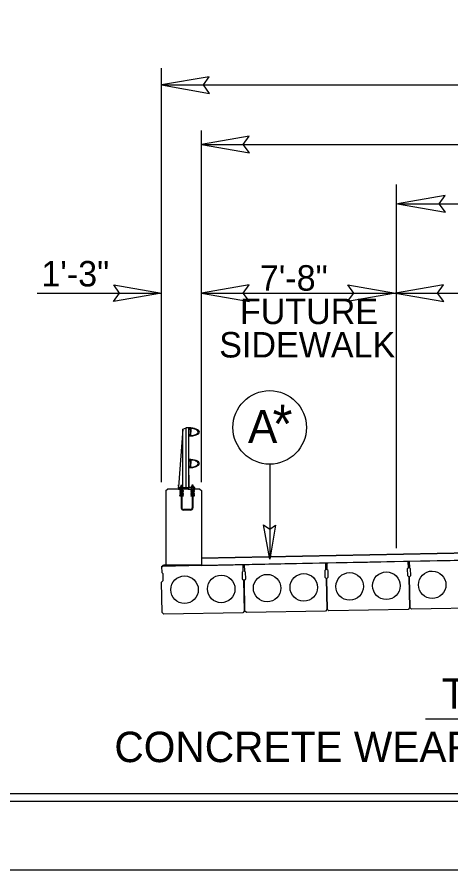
# Model space of a CAD drawing. Extents: x 573732 to 574187, y -53389 to -53257.
# Drawn here: x 573830.28 to 573847.31, y -53388.95 to -53355.48 of the extents above; entities that cross this region are included whole.
import ezdxf

# ---------------------------------------------------------------- set-up
doc = ezdxf.new("R2010")
doc.units = 0
for name, color, linetype in [('Old_Level_60', 7, 'Continuous'), ('Prop Dimension', 7, 'Continuous'), ('Prop Retaining Wall', 7, 'Continuous'), ('Prop Shade Light', 7, 'Continuous'), ('Sheet Cutting Line CELL', 7, 'Continuous'), ('Sheet Plot Border Inside CELL', 7, 'Continuous'), ('Sheet Plot Border Outside CELL', 7, 'Continuous'), ('Sheet Typical CELL', 7, 'Continuous'), ('Typical Bridge Rail Two Bar CELL', 7, 'Continuous'), ('Typical ID Circle CELL', 7, 'Continuous'), ('Typical Pavement Slope CELL', 7, 'Continuous'), ('Typical Pavement Slope Information CELL', 7, 'Continuous'), ('Typical Terminator CELL', 7, 'Continuous'), ('Typical Text ID Circle CELL', 7, 'Continuous'), ('Typical Text Label CELL', 7, 'Continuous')]:
    doc.layers.add(name, color=color, linetype=linetype)

# ---------------------------------------------------------------- blocks, each defined once
blk = doc.blocks.new('BRIDGE RAIL 2 BAR LEFT')
at = {"layer": 'Typical Bridge Rail Two Bar CELL'}
for p, q in [((-2.94, 21.39), (-2.37, 21.57)), ((-1.99, 21.57), (-2.37, 21.57)), ((-2.37, 12.16), (-2.37, 21.57)), ((-1.99, 12.16), (-1.99, 21.57)), ((-1.68, 21.42), (-1.68, 20.91)), ((-2.94, 21.39), (-3.6, 12.34)), ((-2.94, 12.16), (-2.94, 21.39)), ((-1.68, 20.39), (-1.68, 20.91)), ((-2.94, 17.07), (-2.96, 17.07)), ((-1.68, 16.48), (-1.68, 15.97)), ((-1.68, 15.46), (-1.68, 15.97)), ((-3.6, 12.16), (-3.6, 12.34)), ((-3.58, 12.45), (-3.58, 12.62)), ((-3.02, 12.54), (-3.23, 12.54)), ((-3.23, 12.54), (-3.23, 12.36)), ((-3.23, 11.74), (-3.23, 12.16)), ((-3.02, 12.36), (-3.02, 12.54)), ((-3.02, 11.74), (-3.02, 12.16)), ((-1.5, 11.79), (-1.5, 12.2)), ((-1.27, 12.59), (-1.49, 12.59)), ((-1.49, 12.59), (-1.49, 12.41)), ((-1.27, 12.41), (-1.27, 12.59)), ((-1.26, 11.79), (-1.26, 12.2)), ((-5.59, 11.72), (-5.35, 11.97)), ((-5.59, 11.72), (-5.59, 0)), ((-0.24, 11.97), (-5.35, 11.97)), ((-2.88, 11.79), (-3.38, 11.79)), ((-2.88, 11.73), (-3.38, 11.73)), ((-3.17, 11.57), (-3.38, 11.57)), ((-3.17, 11.51), (-3.38, 11.51)), ((-3.17, 11.34), (-3.38, 11.34)), ((-3.17, 11.29), (-3.38, 11.29)), ((-3.17, 11.12), (-3.38, 11.12)), ((-3.17, 11.07), (-3.38, 11.07)), ((-3.17, 10.9), (-3.38, 10.9)), ((-3.17, 10.84), (-3.38, 10.84)), ((-3.17, 11.68), (-3.27, 11.68)), ((-3.17, 11.62), (-3.27, 11.62)), ((-3.17, 11.45), (-3.27, 11.45)), ((-3.17, 11.4), (-3.27, 11.4)), ((-3.17, 11.23), (-3.27, 11.23)), ((-3.17, 11.18), (-3.27, 11.18)), ((-3.17, 11.01), (-3.27, 11.01)), ((-3.17, 10.95), (-3.27, 10.95)), ((-3.09, 11.68), (-3.17, 11.68)), ((-3.17, 11.68), (-3.17, 9.02)), ((-2.99, 11.68), (-3.09, 11.68)), ((-3.09, 11.68), (-3.09, 9.02)), ((-2.99, 11.62), (-3.09, 11.62)), ((-2.88, 11.57), (-3.09, 11.57)), ((-2.88, 11.51), (-3.09, 11.51)), ((-2.99, 11.45), (-3.09, 11.45)), ((-2.99, 11.4), (-3.09, 11.4)), ((-2.88, 11.34), (-3.09, 11.34)), ((-2.88, 11.29), (-3.09, 11.29)), ((-2.99, 11.23), (-3.09, 11.23)), ((-2.99, 11.18), (-3.09, 11.18)), ((-2.88, 11.12), (-3.09, 11.12)), ((-2.88, 11.07), (-3.09, 11.07)), ((-2.99, 11.01), (-3.09, 11.01)), ((-2.99, 10.95), (-3.09, 10.95)), ((-2.88, 10.9), (-3.09, 10.9)), ((-2.88, 10.84), (-3.09, 10.84)), ((-1.14, 11.79), (-1.64, 11.79)), ((-1.14, 11.73), (-1.64, 11.73)), ((-1.43, 11.57), (-1.64, 11.57)), ((-1.43, 11.51), (-1.64, 11.51)), ((-1.43, 11.34), (-1.64, 11.34)), ((-1.43, 11.29), (-1.64, 11.29)), ((-1.43, 11.12), (-1.64, 11.12)), ((-1.43, 11.07), (-1.64, 11.07)), ((-1.43, 10.9), (-1.64, 10.9)), ((-1.43, 10.84), (-1.64, 10.84)), ((-1.43, 11.68), (-1.53, 11.68)), ((-1.43, 11.62), (-1.53, 11.62)), ((-1.43, 11.45), (-1.53, 11.45)), ((-1.43, 11.4), (-1.53, 11.4)), ((-1.43, 11.23), (-1.53, 11.23)), ((-1.43, 11.18), (-1.53, 11.18)), ((-1.43, 11.01), (-1.53, 11.01)), ((-1.43, 10.95), (-1.53, 10.95)), ((-1.34, 11.68), (-1.43, 11.68)), ((-1.43, 11.68), (-1.43, 9.02)), ((-1.25, 11.68), (-1.34, 11.68)), ((-1.34, 11.68), (-1.34, 9.02)), ((-1.25, 11.62), (-1.34, 11.62)), ((-1.14, 11.57), (-1.34, 11.57)), ((-1.14, 11.51), (-1.34, 11.51)), ((-1.25, 11.45), (-1.34, 11.45)), ((-1.25, 11.4), (-1.34, 11.4)), ((-1.14, 11.34), (-1.34, 11.34)), ((-1.14, 11.29), (-1.34, 11.29)), ((-1.25, 11.23), (-1.34, 11.23)), ((-1.25, 11.18), (-1.34, 11.18)), ((-1.14, 11.12), (-1.34, 11.12)), ((-1.14, 11.07), (-1.34, 11.07)), ((-1.25, 11.01), (-1.34, 11.01)), ((-1.25, 10.95), (-1.34, 10.95)), ((-1.14, 10.9), (-1.34, 10.9)), ((-1.14, 10.84), (-1.34, 10.84)), ((-0.24, 11.97), (0, 11.72)), ((0, 11.72), (0, 0)), ((-1.69, 8.76), (-2.82, 8.76)), ((-1.69, 8.67), (-2.82, 8.67)), ((-6.19, -0.27), (-5.95, 0)), ((-5.54, 0), (-5.95, 0)), ((0, 0), (-5.54, 0))]:
    blk.add_line(p, q, dxfattribs=at)
for points in [[(-1.99, 20.25), (-1.99, 20.5), (-1.89, 20.5), (-1.89, 20.46), (-1.9, 20.46), (-1.9, 20.36), (-1.74, 20.36), (-1.72, 20.51), (-1.72, 20.91), (-1.72, 21.3), (-1.74, 21.46), (-1.9, 21.46), (-1.9, 21.36), (-1.89, 21.36), (-1.89, 21.31), (-1.99, 21.31), (-1.99, 21.56)], [(-1.99, 15.32), (-1.99, 15.56), (-1.89, 15.56), (-1.89, 15.52), (-1.9, 15.52), (-1.9, 15.42), (-1.74, 15.42), (-1.72, 15.58), (-1.72, 15.97), (-1.72, 16.37), (-1.74, 16.52), (-1.9, 16.52), (-1.9, 16.42), (-1.89, 16.42), (-1.89, 16.38), (-1.99, 16.38), (-1.99, 16.62)], [(-1.03, 11.97), (-1.03, 12.2), (-1.9, 12.2), (-1.9, 14.14), (-1.99, 14.14), (-1.99, 12.16), (-3.55, 12.16), (-3.55, 12.3), (-3.6, 12.3), (-3.6, 11.97), (-2.85, 11.97), (-2.85, 12.1), (-2.09, 12.1), (-2.09, 11.97), (-1.03, 11.97)], [(-2.91, 12.15), (-2.91, 12.2), (-3.12, 12.2), (-3.34, 12.2), (-3.34, 12.15)], [(-2.97, 12.2), (-2.97, 12.33), (-2.99, 12.36), (-3.25, 12.36), (-3.28, 12.33), (-3.28, 12.2), (-2.97, 12.2), (-3.07, 12.2), (-3.07, 12.33), (-3.04, 12.36), (-3.07, 12.33), (-3.1, 12.36), (-3.15, 12.36), (-3.18, 12.33), (-3.18, 12.2), (-3.18, 12.33), (-3.2, 12.36)], [(-1.16, 12.2), (-1.16, 12.25), (-1.38, 12.25), (-1.59, 12.25), (-1.59, 12.2)], [(-1.22, 12.24), (-1.22, 12.38), (-1.25, 12.41), (-1.51, 12.41), (-1.54, 12.38), (-1.54, 12.24), (-1.22, 12.24), (-1.33, 12.24), (-1.33, 12.38), (-1.3, 12.41), (-1.33, 12.38), (-1.35, 12.41), (-1.41, 12.41), (-1.43, 12.38), (-1.43, 12.24), (-1.43, 12.38), (-1.46, 12.41)], [(-3.38, 11.79), (-3.38, 11.73), (-3.27, 11.68), (-3.27, 11.62), (-3.38, 11.57), (-3.38, 11.51), (-3.27, 11.45), (-3.27, 11.4), (-3.38, 11.34), (-3.38, 11.29), (-3.27, 11.23), (-3.27, 11.18), (-3.38, 11.12), (-3.38, 11.07), (-3.27, 11.01), (-3.27, 10.95), (-3.38, 10.9), (-3.38, 10.84)], [(-2.88, 11.79), (-2.88, 11.73), (-2.99, 11.68), (-2.99, 11.62), (-2.88, 11.57), (-2.88, 11.51), (-2.99, 11.45), (-2.99, 11.4), (-2.88, 11.34), (-2.88, 11.29), (-2.99, 11.23), (-2.99, 11.18), (-2.88, 11.12), (-2.88, 11.07), (-2.99, 11.01), (-2.99, 10.95), (-2.88, 10.9), (-2.88, 10.84)], [(-1.64, 11.79), (-1.64, 11.73), (-1.53, 11.68), (-1.53, 11.62), (-1.64, 11.57), (-1.64, 11.51), (-1.53, 11.45), (-1.53, 11.4), (-1.64, 11.34), (-1.64, 11.29), (-1.53, 11.23), (-1.53, 11.18), (-1.64, 11.12), (-1.64, 11.07), (-1.53, 11.01), (-1.53, 10.95), (-1.64, 10.9), (-1.64, 10.84)], [(-1.14, 11.79), (-1.14, 11.73), (-1.25, 11.68), (-1.25, 11.62), (-1.14, 11.57), (-1.14, 11.51), (-1.25, 11.45), (-1.25, 11.4), (-1.14, 11.34), (-1.14, 11.29), (-1.25, 11.23), (-1.25, 11.18), (-1.14, 11.12), (-1.14, 11.07), (-1.25, 11.01), (-1.25, 10.95), (-1.14, 10.9), (-1.14, 10.84)]]:
    blk.add_lwpolyline(points, dxfattribs=at)
for centre in [(-3.34, 10.98), (-1.18, 10.98)]:
    blk.add_circle(centre, 0.0417, dxfattribs=at)
for centre, radius, start, end in [((-1.64, 21.42), 0.0392, 90, 180), ((-1.64, 20.4), 0.0392, 180, 270), ((-1.64, 16.48), 0.0392, 90, 180), ((-1.64, 15.46), 0.0392, 180, 270), ((-2.82, 9.02), 0.35, 180, 270), ((-2.82, 9.02), 0.267, 180, 270), ((-1.7, 9.02), 0.267, 270, 0), ((-1.69, 9.02), 0.35, 270, 0)]:
    blk.add_arc(centre, radius, start, end, dxfattribs=at)
for centre, major_axis, ratio, start_param, end_param in [((-1.99, 20.91), (1.67, 0), 0.39036, 6.282787, 7.853967), ((-1.64, 20.91), (1.11, 0), 0.495501, 6.282718, 7.853881), ((-1.99, 20.91), (1.67, 0), 0.39036, 4.712404, 6.282787), ((-1.64, 20.91), (1.11, 0), 0.495501, 4.712489, 6.282718), ((-1.99, 15.97), (1.67, 0), 0.39036, 6.282787, 7.853967), ((-1.64, 15.97), (1.11, 0), 0.495501, 6.282718, 7.853881), ((-1.99, 15.97), (1.67, 0), 0.39036, 4.712404, 6.282787), ((-1.64, 15.97), (1.11, 0), 0.495501, 4.712489, 6.282718)]:
    blk.add_ellipse(centre, major_axis=major_axis, ratio=ratio, start_param=start_param, end_param=end_param, dxfattribs=at)

msp = doc.modelspace()

# ---------------------------------------------------------------- linework, layer by layer
at = {"layer": 'Old_Level_60'}
for points in [[(573845.686, -53376.834), (573847.274, -53376.802), (573848.86, -53376.77), (573848.866, -53377.041), (573848.833, -53377.074), (573848.838, -53377.334), (573848.906, -53377.4), (573848.93, -53378.593), (573848.864, -53378.662), (573845.759, -53378.722), (573845.69, -53378.657), (573845.666, -53377.465), (573845.733, -53377.396), (573845.727, -53377.135), (573845.692, -53377.104), (573845.686, -53376.834)], [(573835.966, -53377.025), (573837.554, -53376.994), (573839.139, -53376.962), (573839.145, -53377.233), (573839.113, -53377.266), (573839.117, -53377.525), (573839.186, -53377.592), (573839.209, -53378.785), (573839.144, -53378.854), (573836.039, -53378.914), (573835.969, -53378.849), (573835.945, -53377.657), (573836.013, -53377.588), (573836.007, -53377.327), (573835.972, -53377.296), (573835.966, -53377.025)], [(573839.206, -53376.962), (573840.794, -53376.931), (573842.379, -53376.899), (573842.385, -53377.169), (573842.353, -53377.203), (573842.357, -53377.462), (573842.426, -53377.528), (573842.449, -53378.722), (573842.384, -53378.79), (573839.279, -53378.851), (573839.209, -53378.785), (573839.185, -53377.594), (573839.253, -53377.524), (573839.247, -53377.264), (573839.212, -53377.233), (573839.206, -53376.962)], [(573842.446, -53376.897), (573844.034, -53376.866), (573845.62, -53376.833), (573845.626, -53377.104), (573845.593, -53377.138), (573845.598, -53377.397), (573845.666, -53377.463), (573845.69, -53378.657), (573845.624, -53378.725), (573842.519, -53378.786), (573842.45, -53378.72), (573842.426, -53377.528), (573842.493, -53377.459), (573842.487, -53377.199), (573842.452, -53377.168), (573842.446, -53376.897)]]:
    msp.add_lwpolyline(points, dxfattribs=at)
for centre in [(573836.852, -53377.953), (573838.292, -53377.924), (573840.092, -53377.89), (573841.532, -53377.861), (573843.333, -53377.824), (573844.773, -53377.796), (573846.573, -53377.761)]:
    msp.add_ellipse(centre, major_axis=(0.001, 0.54), ratio=0.999904, dxfattribs=at)
at = {"layer": 'Prop Dimension'}
for p, q in [((573835.945, -53373.728), (573835.945, -53357.486)), ((573835.945, -53358.149), (573874.781, -53358.149)), ((573837.514, -53373.728), (573837.514, -53359.942)), ((573837.514, -53360.479), (573873.174, -53360.479)), ((573845.175, -53376.328), (573845.175, -53362.052)), ((573845.206, -53362.808), (573869.166, -53362.808)), ((573831.067, -53366.315), (573835.945, -53366.315)), ((573837.514, -53366.315), (573845.138, -53366.315)), ((573845.138, -53366.315), (573857.171, -53366.315))]:
    msp.add_line(p, q, dxfattribs=at)
at = {"layer": 'Prop Shade Light'}
for p, q in [((573857.004, -53376.325), (573837.514, -53376.715)), ((573837.514, -53376.715), (573837.519, -53376.998)), ((573837.519, -53376.998), (573857.01, -53376.608))]:
    msp.add_line(p, q, dxfattribs=at)
at = {"layer": 'Sheet Cutting Line CELL'}
msp.add_line((573782.222, -53388.948), (573984.302, -53388.948), dxfattribs=at)
at = {"layer": 'Sheet Plot Border Inside CELL'}
msp.add_lwpolyline([(573983.762, -53259.642), (573783.782, -53259.642), (573783.782, -53386.254), (573983.762, -53386.254)], close=True, dxfattribs=at)
at = {"layer": 'Sheet Plot Border Outside CELL'}
msp.add_lwpolyline([(573984.302, -53256.948), (573782.222, -53256.948), (573782.222, -53388.948), (573984.302, -53388.948)], close=True, dxfattribs=at)
at = {"layer": 'Sheet Typical CELL'}
msp.add_lwpolyline([(573982.262, -53259.948), (573802.262, -53259.948), (573802.262, -53385.948), (573982.262, -53385.948)], close=True, dxfattribs=at)
at = {"layer": 'Typical ID Circle CELL'}
msp.add_line((573840.193, -53373.028), (573840.193, -53376.756), dxfattribs=at)
msp.add_circle((573840.193, -53371.586), 1.443, dxfattribs=at)
at = {"layer": 'Typical Pavement Slope CELL'}
for p, q in [((573837.514, -53376.715), (573857.171, -53376.322)), ((573837.514, -53376.995), (573857.176, -53376.605)), ((573837.514, -53376.712), (573837.514, -53376.995))]:
    msp.add_line(p, q, dxfattribs=at)
at = {"layer": 'Typical Terminator CELL'}
for points in [[(573837.82, -53357.827), (573835.945, -53358.149), (573837.831, -53358.483), (573837.591, -53358.149)], [(573839.388, -53360.156), (573837.514, -53360.479), (573839.399, -53360.812), (573839.159, -53360.479)], [(573847.081, -53362.485), (573845.206, -53362.808), (573847.091, -53363.141), (573846.852, -53362.808)], [(573834.071, -53365.992), (573835.945, -53366.315), (573834.06, -53366.648), (573834.3, -53366.315)], [(573839.388, -53365.992), (573837.514, -53366.315), (573839.399, -53366.648), (573839.159, -53366.315)], [(573843.263, -53365.992), (573845.138, -53366.315), (573843.252, -53366.648), (573843.492, -53366.315)], [(573847.012, -53365.992), (573845.138, -53366.315), (573847.023, -53366.648), (573846.783, -53366.315)], [(573840.423, -53375.42), (573840.193, -53376.756), (573839.955, -53375.413), (573840.193, -53375.583)]]:
    msp.add_lwpolyline(points, close=True, dxfattribs=at)
at = {"layer": 'Typical Text Label CELL'}
msp.add_line((573846.304, -53383.022), (573867.908, -53383.022), dxfattribs=at)

# ---------------------------------------------------------------- block references
at = {"layer": 'Prop Retaining Wall', "xscale": 0.25, "yscale": 0.25}
msp.add_blockref('BRIDGE RAIL 2 BAR LEFT', (573837.514, -53376.995), dxfattribs=at)

# ---------------------------------------------------------------- texts
at = {"layer": 'Typical Pavement Slope Information CELL'}
msp.add_text('1\'-3"', height=1, rotation=360, dxfattribs=at).set_placement((573831.232, -53366.055))
for s, p in [('7\'-8"', (573839.808, -53366.22)), ('FUTURE', (573839.026, -53367.531)), ('SIDEWALK', (573838.213, -53368.842))]:
    msp.add_text(s, height=1, dxfattribs=at).set_placement(p)
at = {"layer": 'Typical Text ID Circle CELL'}
for s, height, p in [('*', 1.5, (573840.307, -53372.195)), ('A ', 1.2912, (573839.341, -53372.195))]:
    msp.add_text(s, height=height, dxfattribs=at).set_placement(p)
at = {"layer": 'Typical Text Label CELL'}
msp.add_text('TYPICAL SECTION NO.  ', height=1.19356, rotation=360, dxfattribs=at).set_placement((573846.944, -53382.622))
msp.add_text('CONCRETE WEARING SURFACE (STRUCTURES PAY ITEM)', height=1.19356, dxfattribs=at).set_placement((573834.098, -53384.718))

doc.saveas('drawing.dxf')
